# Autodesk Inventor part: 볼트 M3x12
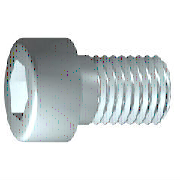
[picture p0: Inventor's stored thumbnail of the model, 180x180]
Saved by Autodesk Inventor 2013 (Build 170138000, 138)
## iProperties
IsCustomPart: 0
Created: 2012-02
Part Number: 볼트 M3x12
Material: 강철, 연강
Description: 6각머리 태핑 나사
Document SubType Name: Modeling
Standard: KS B 1003
Designer: mduedu
Standards Organization: KS
Language: ko-KR
Size Designation: M 3 x 12
Categories: <MemberInstance><Categories><Category DisplayName="조임쇠" InternalName="e4da775c-781d-43d5-af7c-5136215cf5a6" Mnemonic="FSTN"><Category DisplayName="볼트" InternalN
Density: 1 g/cm^3
Author: mduedu
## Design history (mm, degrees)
sketch "스케치1"
  geometry: L1 (-0.867, 0)-(12, 0); L2 (12, 0)-(12, 1.5); L3 (12, 1.5)-(1.25, 1.5); L4 (1.25, 1.5)-(0.943, 1.5); L5 (0.943, 1.5)-(0, 1.5); L6 (0, 1.5)-(0, 2.75); L7 (0, 2.75)-(-3, 2.75); L8 (-3, 2.75)-(-3, 1.443); L9 (-3, 1.443)-(-1.7, 1.443); L10 (-1.7, 1.443)-(-0.867, 0); L11 (-6, 0)-(15, 0) reference; L12 (0, -0.55)-(0, 3.3) reference; L13 (1.25, 1.5)-(0, 1.5)
  constraints: 22 end point, 6 parallel, 2 collinear, 2 perpendicular, 1 horizontal, 1 point on line
  dimensions: "d1" = 10.75 distance from line of L3.end L2 (= GEL); "d2" = 0.30683 distance of L4.end L3.end (computed from GAL); "d3" = 3 distance between parallel lines of L8 L6 (= KOH); "d4" = 1.3 distance of L8.end L9.end (= INTI); "d5" = 60 deg angle of L10 L1; "d6" = 3 diameter of L3 L1 (= GD); "d7" = 3 diameter of L5 L1 (= BDM); "d8" = 2.88675 diameter of L9 L1 (= 1.1547 x SW); "d9" = 5.5 diameter of L7 L1 (= KOD); "d26" = 12 distance between parallel lines of L12 L2 (= NLG)
revolve "본체" sketch "스케치1" stored, may be unused: angle "d10" = 90 deg
sketch "스케치2"
  geometry: L1 (0, -3.85)-(0, 3.85) reference; L2 (-3.85, 0)-(3.85, 0) reference; L3 (1.443, 0)-(0.722, -1.25); L4 (0.722, -1.25)-(-0.722, -1.25); L5 (-0.722, -1.25)-(-1.443, 0); L6 (-1.443, 0)-(-0.722, 1.25); L7 (-0.722, 1.25)-(0.722, 1.25); L8 (0.722, 1.25)-(1.443, 0); 2 further points
  constraints: 12 end point, 1 coincident, 1 horizontal alignment, 1 point on line, 12 other
extrude "슬롯" join sketch "스케치2" stored distance "d11" = 10; taper "d12" = 0 deg
workplane "Work Plane1"
fillet "Fillet2" dims "d30" = 0.1 (= R)
body "Solid1"
fillet "모깎기1" dims "d17" = 0.3 (= RR)
feature "스레드" dims "d13" = 10.75 (= GEL), "d14" = 0
chamfer "모따기1" distance "d15" = 0.30673 (= -0.5 x SPD + 0.5 x GD); stored, may be unused: second distance "d16" = 0.30673 (= GUL), angle "d27" = 45 deg
other parameters: "GD" = 3 (= NND) [user parameter; used in 2 equation terms], "NLG" = 12 [user parameter; used in 1 equation term], "GEL" = 10.75 [user parameter; used in 2 equation terms], "KOD" = 5.5 [user parameter; used in 1 equation term], "KOH" = 3 [user parameter; used in 1 equation term], "INTI" = 1.3 [user parameter; used in 1 equation term], "GAL" = 0.30673 (= 0.61345 x PTC) [user parameter; used in 1 equation term], "GUL" = 0.30673 (= 0.61345 x PTC) [user parameter; used in 1 equation term], "BDM" = 3 (= NND) [user parameter; used in 1 equation term], "SW" = 2.5 [user parameter; used in 2 equation terms], "RR" = 0.3 [user parameter; used in 1 equation term], "SPD" = 2.38655 (= NND - 1.2269 x PTC) [user parameter; used in 1 equation term], "d19" = 0, "d28" = 0, "d29" = 0, "R" = 0.1 [user parameter; used in 1 equation term], "PHH" = 0.1 [user parameter], "GD1" = 2.38655 (= THREADDIA - 1.2269 x PTC) [user parameter], "THREADDIA" = 3 [user parameter; used in 1 equation term], "FAWI" = 45 deg [user parameter], "PTC" = 0.5 [user parameter; used in 5 equation terms], "NND" = 3 [user parameter; used in 3 equation terms], "TOA" = 30 deg [user parameter], "E0" = 2.8875 (= 1.155 x SW) [user parameter]
